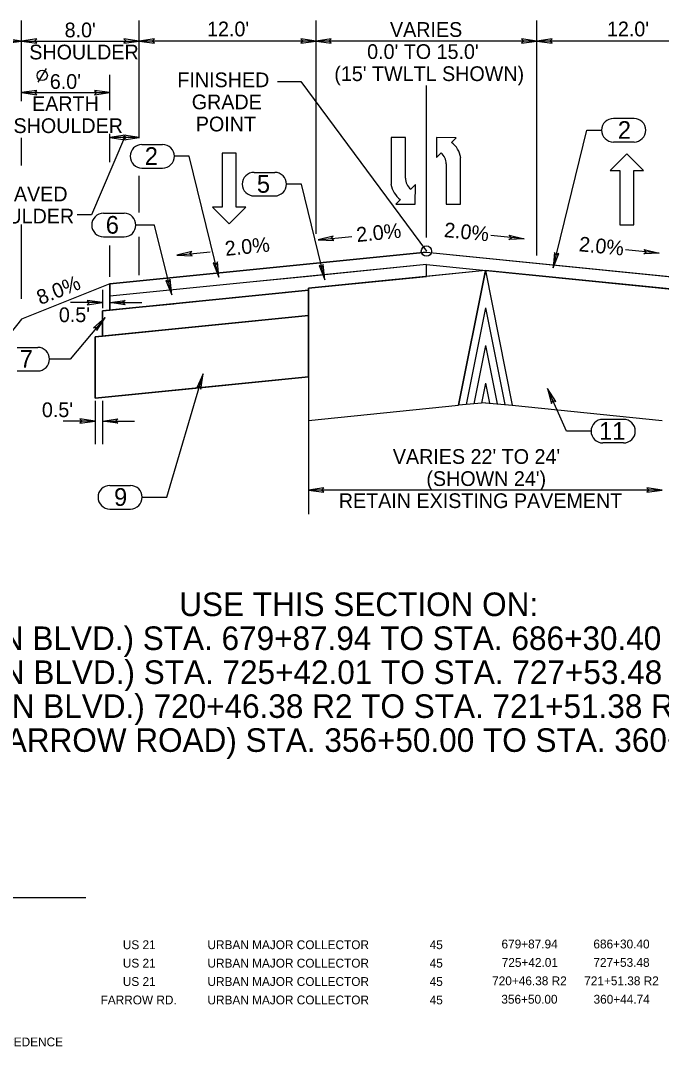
# Model space of a CAD drawing. Extents: x 2003207 to 2014043, y 843846 to 860154.
# Drawn here: x 2013864.3 to 2013907.8, y 844567.2 to 844636.8 of the extents above; entities that cross this region are included whole.
import ezdxf

# ---------------------------------------------------------------- set-up
doc = ezdxf.new("R2010")
doc.units = 0
for name, color, linetype in [('RD_EX_Road', 7, 'Continuous'), ('RD_EX_Road_txCode', 7, 'Continuous'), ('RD_QTY_Base_Course', 7, 'Continuous'), ('RD_QTY_ConcPave', 7, 'Continuous'), ('RD_QTY_Intermediate', 7, 'Continuous'), ('RD_QTY_PermVeg', 7, 'Continuous'), ('RD_QTY_Surf_Course', 7, 'Continuous'), ('RD_SHT_Bndy', 7, 'Continuous'), ('RD_SHT_TX', 7, 'Continuous'), ('RD_TX_Misc2', 7, 'Continuous'), ('RD_TX_TypSect', 7, 'Continuous')]:
    doc.layers.add(name, color=color, linetype=linetype)

msp = doc.modelspace()

# ---------------------------------------------------------------- linework, layer by layer
at = {"layer": 'RD_EX_Road'}
for p, q in [((2013895.892, 844619.853), (2013883.892, 844618.653)), ((2013895.892, 844619.853), (2013894.063, 844610.705)), ((2013894.063, 844610.705), (2013895.892, 844619.853)), ((2013895.892, 844619.853), (2013897.722, 844610.705)), ((2013907.892, 844618.653), (2013895.892, 844619.853)), ((2013895.892, 844619.853), (2013897.722, 844610.705)), ((2013883.892, 844618.653), (2013883.892, 844609.657)), ((2013895.892, 844617.304), (2013894.581, 844610.748)), ((2013895.892, 844617.304), (2013897.203, 844610.748)), ((2013895.892, 844614.754), (2013895.1, 844610.791)), ((2013895.892, 844614.754), (2013896.685, 844610.791)), ((2013895.892, 844612.205), (2013895.618, 844610.835)), ((2013895.892, 844612.205), (2013896.166, 844610.835)), ((2013883.892, 844609.657), (2013894.063, 844610.705)), ((2013895.892, 844610.857), (2013894.063, 844610.705)), ((2013895.892, 844610.857), (2013897.722, 844610.705)), ((2013897.722, 844610.705), (2013907.892, 844609.657))]:
    msp.add_line(p, q, dxfattribs=at)
at = {"layer": 'RD_EX_Road_txCode'}
msp.add_circle((2013891.892, 844621.17), 0.35, dxfattribs=at)
at = {"layer": 'RD_QTY_Base_Course'}
for p, q in [((2013883.892, 844616.801), (2013883.892, 844618.506)), ((2013872.392, 844617.356), (2013869.892, 844617.106)), ((2013869.892, 844617.106), (2013869.892, 844615.401)), ((2013874.744, 844617.591), (2013872.392, 844617.356)), ((2013869.892, 844615.401), (2013883.892, 844616.801)), ((2013883.892, 844616.801), (2013871.892, 844615.601)), ((2013883.892, 844612.634), (2013883.892, 844616.801)), ((2013871.892, 844615.601), (2013869.392, 844615.351)), ((2013869.392, 844615.351), (2013869.892, 844615.401)), ((2013869.392, 844611.184), (2013869.392, 844615.351)), ((2013869.392, 844615.351), (2013869.392, 844611.184)), ((2013883.892, 844612.634), (2013869.392, 844611.184))]:
    msp.add_line(p, q, dxfattribs=at)
for points in [[(2013883.892, 844618.506), (2013874.893, 844617.606), (2013874.887, 844617.605), (2013874.744, 844617.591)], [(2013869.392, 844611.184), (2013876.451, 844611.89), (2013883.892, 844612.634)]]:
    msp.add_lwpolyline(points, dxfattribs=at)
at = {"layer": 'RD_QTY_ConcPave'}
for p, q in [((2013869.892, 844617.106), (2013870.392, 844617.156)), ((2013869.892, 844615.401), (2013869.892, 844617.106)), ((2013883.892, 844616.801), (2013869.892, 844615.401))]:
    msp.add_line(p, q, dxfattribs=at)
at = {"layer": 'RD_QTY_Intermediate'}
for p, q in [((2013879.892, 844619.053), (2013870.392, 844618.103)), ((2013883.892, 844619.453), (2013879.892, 844619.053)), ((2013883.892, 844618.506), (2013869.933, 844617.11)), ((2013874.893, 844617.606), (2013883.892, 844618.506)), ((2013883.892, 844618.506), (2013883.892, 844618.653)), ((2013870.392, 844617.156), (2013870.392, 844618.103)), ((2013870.392, 844618.103), (2013870.392, 844617.156)), ((2013874.744, 844617.591), (2013874.887, 844617.605))]:
    msp.add_line(p, q, dxfattribs=at)
for points in [[(2013883.892, 844618.653), (2013891.892, 844619.453), (2013891.892, 844620.253), (2013883.892, 844619.453)], [(2013870.392, 844617.156), (2013872.392, 844617.356), (2013874.744, 844617.591)], [(2013874.887, 844617.605), (2013874.892, 844617.616), (2013874.893, 844617.606)]]:
    msp.add_lwpolyline(points, dxfattribs=at)
at = {"layer": 'RD_QTY_PermVeg'}
for p, q in [((2013870.392, 844618.936), (2013864.392, 844616.536)), ((2013864.392, 844616.536), (2013850.392, 844599.036))]:
    msp.add_line(p, q, dxfattribs=at)
at = {"layer": 'RD_QTY_Surf_Course'}
for p, q in [((2013891.892, 844621.086), (2013870.392, 844618.936)), ((2013891.892, 844621.086), (2013913.392, 844618.936)), ((2013891.892, 844620.253), (2013870.392, 844618.103)), ((2013891.892, 844620.253), (2013913.392, 844618.103)), ((2013870.392, 844618.936), (2013870.392, 844618.103))]:
    msp.add_line(p, q, dxfattribs=at)
msp.add_lwpolyline([(2013870.392, 844618.936), (2013891.892, 844621.086), (2013913.392, 844618.936), (2013913.392, 844618.103), (2013895.892, 844619.853), (2013891.892, 844619.453), (2013891.892, 844620.253), (2013870.392, 844618.103)], close=True, dxfattribs=at)
at = {"layer": 'RD_SHT_Bndy'}
msp.add_line((2013868.755, 844577.242), (2013845.755, 844577.242), dxfattribs=at)
at = {"layer": 'RD_TX_Misc2'}
for p, q in [((2013905.983, 844630.175), (2013904.583, 844630.175)), ((2013872.577, 844628.407), (2013873.977, 844628.407)), ((2013905.983, 844628.575), (2013904.583, 844628.575)), ((2013872.577, 844626.807), (2013873.977, 844626.807)), ((2013880.189, 844626.515), (2013881.589, 844626.515)), ((2013880.189, 844624.915), (2013881.589, 844624.915)), ((2013869.962, 844623.735), (2013871.362, 844623.735)), ((2013869.962, 844622.135), (2013871.362, 844622.135)), ((2013864.098, 844614.63), (2013865.498, 844614.63)), ((2013864.098, 844613.03), (2013865.498, 844613.03)), ((2013905.269, 844609.742), (2013903.869, 844609.742)), ((2013905.269, 844608.142), (2013903.869, 844608.142)), ((2013870.391, 844605.255), (2013871.791, 844605.255)), ((2013870.391, 844603.655), (2013871.791, 844603.655))]:
    msp.add_line(p, q, dxfattribs=at)
for centre, start, end in [((2013904.583, 844629.375), 90, 270), ((2013905.983, 844629.375), 270, 90), ((2013872.577, 844627.607), 90, 270), ((2013873.977, 844627.607), 270, 90), ((2013880.189, 844625.715), 90, 270), ((2013881.589, 844625.715), 270, 90), ((2013869.962, 844622.935), 90, 270), ((2013871.362, 844622.935), 270, 90), ((2013865.498, 844613.83), 270, 90), ((2013903.869, 844608.942), 90, 270), ((2013905.269, 844608.942), 270, 90), ((2013870.391, 844604.455), 90, 270), ((2013871.791, 844604.455), 270, 90)]:
    msp.add_arc(centre, 0.8, start, end, dxfattribs=at)
at = {"layer": 'RD_TX_TypSect'}
for p, q in [((2013864.392, 844631.344), (2013864.392, 844636.824)), ((2013872.392, 844628.846), (2013872.392, 844636.824)), ((2013884.392, 844622.345), (2013884.392, 844636.824)), ((2013899.392, 844620.872), (2013899.392, 844636.824)), ((2013850.392, 844635.433), (2013864.392, 844635.433)), ((2013864.392, 844635.433), (2013872.392, 844635.433)), ((2013884.392, 844635.433), (2013872.392, 844635.433)), ((2013899.392, 844635.433), (2013884.392, 844635.433)), ((2013911.392, 844635.433), (2013899.392, 844635.433)), ((2013865.52, 844632.627), (2013866.086, 844633.57)), ((2013870.392, 844630.733), (2013870.392, 844633.14)), ((2013891.892, 844622.086), (2013891.892, 844632.415)), ((2013864.392, 844631.933), (2013870.392, 844631.933)), ((2013864.392, 844626.986), (2013864.392, 844628.865)), ((2013870.392, 844627.209), (2013870.392, 844629.14)), ((2013872.392, 844628.883), (2013870.392, 844628.883)), ((2013889.489, 844628.875), (2013889.489, 844625.71)), ((2013890.479, 844628.875), (2013889.489, 844628.875)), ((2013890.479, 844626.13), (2013890.479, 844628.875)), ((2013892.579, 844628.875), (2013892.564, 844627.525)), ((2013893.899, 844628.86), (2013892.579, 844628.875)), ((2013893.584, 844628.545), (2013893.899, 844628.86)), ((2013892.564, 844627.525), (2013892.879, 844627.84)), ((2013894.214, 844624.345), (2013894.214, 844627.51)), ((2013893.224, 844627.09), (2013893.224, 844624.345)), ((2013872.392, 844623.783), (2013872.392, 844626.287)), ((2013891.139, 844625.695), (2013890.824, 844625.38)), ((2013891.124, 844624.345), (2013891.139, 844625.695)), ((2013890.119, 844624.675), (2013889.804, 844624.36)), ((2013889.804, 844624.36), (2013891.124, 844624.345)), ((2013893.224, 844624.345), (2013894.214, 844624.345)), ((2013864.392, 844617.928), (2013864.392, 844622.965)), ((2013872.392, 844619.537), (2013872.392, 844622.125)), ((2013884.549, 844621.926), (2013886.826, 844622.154)), ((2013898.529, 844621.99), (2013896.252, 844622.218)), ((2013870.392, 844619.428), (2013870.392, 844621.542)), ((2013874.937, 844620.897), (2013877.213, 844621.124)), ((2013907.688, 844621.026), (2013905.411, 844621.253)), ((2013869.892, 844618.53), (2013869.892, 844617.302)), ((2013869.892, 844617.671), (2013867.725, 844617.671)), ((2013870.392, 844617.671), (2013872.56, 844617.671)), ((2013869.392, 844611.002), (2013869.392, 844608.061)), ((2013869.892, 844611.002), (2013869.892, 844608.061)), ((2013869.392, 844609.63), (2013867.225, 844609.63)), ((2013869.892, 844609.63), (2013872.06, 844609.63)), ((2013883.892, 844609.828), (2013883.892, 844603.307)), ((2013907.892, 844604.939), (2013883.892, 844604.939))]:
    msp.add_line(p, q, dxfattribs=at)
for points in [[(2013864.392, 844635.433), (2013863.354, 844635.583), (2013863.514, 844635.433), (2013863.354, 844635.283)], [(2013864.392, 844635.433), (2013865.431, 844635.283), (2013865.271, 844635.433), (2013865.431, 844635.583)], [(2013872.392, 844635.433), (2013871.354, 844635.583), (2013871.514, 844635.433), (2013871.354, 844635.283)], [(2013872.392, 844635.433), (2013873.431, 844635.283), (2013873.271, 844635.433), (2013873.431, 844635.583)], [(2013884.392, 844635.433), (2013883.354, 844635.583), (2013883.514, 844635.433), (2013883.354, 844635.283)], [(2013884.392, 844635.433), (2013885.431, 844635.283), (2013885.271, 844635.433), (2013885.431, 844635.583)], [(2013899.392, 844635.433), (2013898.354, 844635.583), (2013898.514, 844635.433), (2013898.354, 844635.283)], [(2013899.392, 844635.433), (2013900.431, 844635.283), (2013900.271, 844635.433), (2013900.431, 844635.583)], [(2013864.392, 844631.933), (2013865.431, 844631.783), (2013865.271, 844631.933), (2013865.431, 844632.083)], [(2013870.392, 844631.933), (2013869.354, 844632.083), (2013869.514, 844631.933), (2013869.354, 844631.783)], [(2013870.392, 844628.883), (2013871.431, 844628.733), (2013871.271, 844628.883), (2013871.431, 844629.033)], [(2013872.392, 844628.883), (2013871.354, 844629.033), (2013871.514, 844628.883), (2013871.354, 844628.733)], [(2013878.974, 844627.809), (2013878.014, 844627.809), (2013878.014, 844624.14), (2013877.363, 844624.14), (2013878.494, 844623.009), (2013879.625, 844624.14), (2013878.974, 844624.14)], [(2013905.014, 844622.961), (2013905.974, 844622.961), (2013905.974, 844626.63), (2013906.625, 844626.63), (2013905.494, 844627.761), (2013904.363, 844626.63), (2013905.014, 844626.63)], [(2013884.549, 844621.926), (2013885.597, 844621.88), (2013885.423, 844622.013), (2013885.567, 844622.179)], [(2013898.529, 844621.99), (2013897.481, 844621.945), (2013897.655, 844622.078), (2013897.51, 844622.243)], [(2013874.937, 844620.897), (2013875.985, 844620.851), (2013875.811, 844620.984), (2013875.955, 844621.149)], [(2013907.688, 844621.026), (2013906.64, 844620.98), (2013906.814, 844621.113), (2013906.669, 844621.278)], [(2013877.798, 844619.387), (2013877.696, 844620.431), (2013877.589, 844620.24), (2013877.405, 844620.36)], [(2013900.489, 844620.038), (2013900.881, 844621.011), (2013900.698, 844620.891), (2013900.59, 844621.082)], [(2013884.99, 844619.211), (2013884.888, 844620.255), (2013884.781, 844620.064), (2013884.597, 844620.184)], [(2013874.593, 844618.208), (2013874.492, 844619.252), (2013874.384, 844619.061), (2013874.2, 844619.181)], [(2013869.892, 844617.671), (2013868.854, 844617.82), (2013869.014, 844617.671), (2013868.854, 844617.521)], [(2013870.392, 844617.671), (2013871.431, 844617.82), (2013871.271, 844617.671), (2013871.431, 844617.521)], [(2013870.074, 844616.666), (2013869.291, 844615.966), (2013869.509, 844615.993), (2013869.521, 844615.774)], [(2013876.731, 844612.837), (2013876.293, 844611.883), (2013876.482, 844611.994), (2013876.58, 844611.798)], [(2013900.106, 844611.834), (2013900.392, 844610.824), (2013900.464, 844611.032), (2013900.666, 844610.946)], [(2013869.392, 844609.63), (2013868.354, 844609.78), (2013868.514, 844609.63), (2013868.354, 844609.48)], [(2013869.892, 844609.63), (2013870.931, 844609.78), (2013870.771, 844609.63), (2013870.931, 844609.48)], [(2013883.892, 844604.939), (2013884.931, 844604.789), (2013884.771, 844604.939), (2013884.931, 844605.089)], [(2013907.892, 844604.939), (2013906.854, 844605.089), (2013907.014, 844604.939), (2013906.854, 844604.789)]]:
    msp.add_lwpolyline(points, close=True, dxfattribs=at)
for points in [[(2013881.787, 844632.69), (2013883.356, 844632.69), (2013891.892, 844621.17)], [(2013871.392, 844628.883), (2013869.152, 844623.637), (2013868.165, 844623.637)], [(2013900.489, 844620.038), (2013902.775, 844629.375), (2013903.783, 844629.375)], [(2013877.798, 844619.387), (2013875.785, 844627.607), (2013874.777, 844627.607)], [(2013884.99, 844619.211), (2013883.397, 844625.715), (2013882.389, 844625.715)], [(2013874.593, 844618.208), (2013873.436, 844622.935), (2013872.162, 844622.935)], [(2013870.074, 844616.666), (2013867.701, 844613.83), (2013866.298, 844613.83)], [(2013872.591, 844604.455), (2013874.256, 844604.455), (2013876.731, 844612.837)], [(2013903.069, 844608.942), (2013901.404, 844608.942), (2013900.106, 844611.834)]]:
    msp.add_lwpolyline(points, dxfattribs=at)
msp.add_circle((2013865.803, 844633.098), 0.35, dxfattribs=at)
for centre, radius, start, end in [((2013892.661, 844627.272), 1.576, 8.67607, 53.98777), ((2013892.247, 844627.093), 0.983, 0, 49.65818), ((2013891.456, 844626.127), 0.983, 180, 229.65817), ((2013891.042, 844625.947), 1.576, 188.67607, 233.98777)]:
    msp.add_arc(centre, radius, start, end, dxfattribs=at)

# ---------------------------------------------------------------- texts
at = {"layer": 'RD_EX_Road_txCode'}
for s, height, p in [('USE THIS SECTION ON:', 1.6, (2013875.105, 844596.386)), ('US 21 (WILSON BLVD.) STA. 679+87.94 TO STA. 686+30.40', 1.6, (2013848.85, 844594.081)), ('US 21 (WILSON BLVD.) STA. 725+42.01 TO STA. 727+53.48', 1.6, (2013848.913, 844591.775)), ('US21EX (WILSON BLVD.) 720+46.38 R2 TO STA. 721+51.38 R2', 1.6, (2013847.325, 844589.47)), ('FARROW (SC-555 FARROW ROAD) STA. 356+50.00 TO STA. 360+44.74', 1.6, (2013843.357, 844587.164)), (' TYPICAL SECTIONS TAKE PRECEDENCE', 0.6, (2013851.208, 844567.168))]:
    msp.add_text(s, height=height, dxfattribs=at).set_placement(p)
at = {"layer": 'RD_SHT_TX'}
for s, p in [('US 21', (2013871.276, 844573.768)), ('URBAN MAJOR COLLECTOR', (2013877.023, 844573.768)), ('45', (2013892.109, 844573.768)), ('679+87.94', (2013896.987, 844573.817)), ('686+30.40', (2013903.226, 844573.817)), ('US 21', (2013871.276, 844572.518)), ('URBAN MAJOR COLLECTOR', (2013877.023, 844572.518)), ('45', (2013892.109, 844572.518)), ('725+42.01', (2013897.004, 844572.567)), ('727+53.48', (2013903.226, 844572.567)), ('US 21', (2013871.276, 844571.268)), ('URBAN MAJOR COLLECTOR', (2013877.023, 844571.268)), ('45', (2013892.109, 844571.268)), ('720+46.38 R2 ', (2013896.353, 844571.317)), ('721+51.38 R2', (2013902.603, 844571.317)), ('FARROW RD.', (2013869.765, 844570.018)), ('URBAN MAJOR COLLECTOR', (2013877.023, 844570.018)), ('45', (2013892.109, 844570.018)), ('356+50.00', (2013896.976, 844570.067)), ('360+44.74', (2013903.237, 844570.067))]:
    msp.add_text(s, height=0.6, dxfattribs=at).set_placement(p)
at = {"layer": 'RD_TX_Misc2'}
for s, p in [('2', (2013904.888, 844628.791)), ('2', (2013872.767, 844627.022)), ('5', (2013880.379, 844625.13)), ('6', (2013870.118, 844622.351)), ('7', (2013864.276, 844613.245)), ('11', (2013903.609, 844608.357)), ('9', (2013870.682, 844603.87))]:
    msp.add_text(s, height=1.2, dxfattribs=at).set_placement(p)
at = {"layer": 'RD_TX_TypSect'}
for s, p in [("8.0'", (2013867.324, 844635.683)), ("12.0'", (2013876.994, 844635.75)), ('VARIES', (2013889.416, 844635.714)), ("12.0'", (2013904.146, 844635.75)), ('SHOULDER', (2013864.924, 844634.183)), ("0.0' TO 15.0'", (2013887.865, 844634.214)), ("(15' TWLTL SHOWN)", (2013885.636, 844632.714)), ("6.0'", (2013866.318, 844632.183)), ('FINISHED', (2013874.98, 844632.296)), ('EARTH', (2013865.113, 844630.683)), ('GRADE', (2013875.956, 844630.796)), ('SHOULDER', (2013863.853, 844629.183)), ('POINT', (2013876.231, 844629.296)), ("2.0' PAVED", (2013860.503, 844624.544)), ('SHOULDER', (2013860.542, 844623.044)), ("0.5'", (2013866.933, 844616.345)), ("0.5'", (2013865.781, 844609.894)), ("VARIES 22' TO 24'", (2013889.609, 844606.719)), ("(SHOWN 24')", (2013891.885, 844605.219)), ('RETAIN EXISTING PAVEMENT', (2013885.94, 844603.719))]:
    msp.add_text(s, height=1, dxfattribs=at).set_placement(p)
for s, rotation, p in [('2.0%', 5.71059, (2013887.182, 844621.779)), ('2.0%', 354.28941, (2013893.052, 844622.128)), ('2.0%', 5.71059, (2013878.257, 844620.836)), ('2.0%', 354.28941, (2013902.211, 844621.163)), ('8.0%', 21.80141, (2013865.674, 844617.496))]:
    msp.add_text(s, height=1, rotation=rotation, dxfattribs=at).set_placement(p)

doc.saveas('drawing.dxf')
